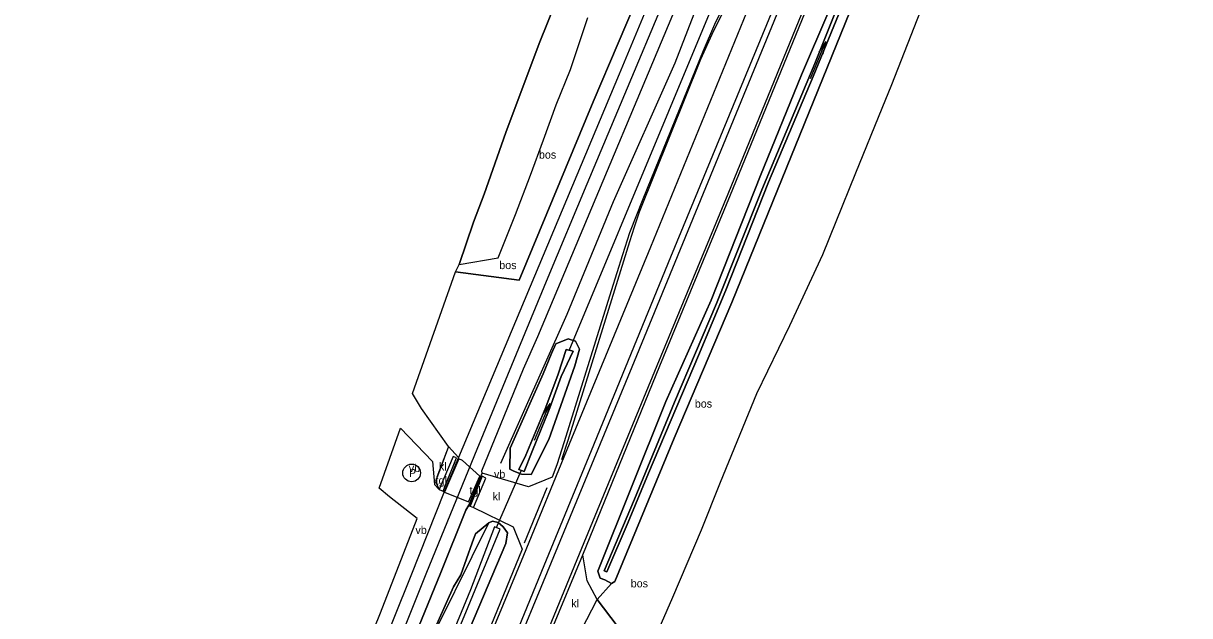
# Model space of a CAD drawing. Extents: x 154825 to 158680, y 370717 to 378075.
# Drawn here: x 158304.8 to 158450.6, y 370834.3 to 370908.4 of the extents above; entities that cross this region are included whole.
import ezdxf

# ---------------------------------------------------------------- set-up
doc = ezdxf.new("R2010")
doc.units = 0
for name, color, linetype in [('bos(vs)', 7, 'Continuous'), ('cultuurscheiding', 7, 'Continuous'), ('deelstreep', 7, 'Continuous'), ('deelstreep(9-3)', 7, 'Continuous'), ('driehoekmarkering', 7, 'Continuous'), ('duiker lijn', 7, 'Continuous'), ('hoogteverschillijn', 7, 'Continuous'), ('insteek sloot', 7, 'Continuous'), ('klinkerverharding(vs)', 7, 'Continuous'), ('maaiveldlijn algemeen - bomenrij', 7, 'Continuous'), ('maaiveldlijn algemeen - gesloten verharding', 7, 'Continuous'), ('maaiveldlijn algemeen - onverhard', 7, 'Continuous'), ('maaiveldlijn algemeen - open verharding', 7, 'Continuous'), ('maaiveldlijn algemeen - tegelverharding', 7, 'Continuous'), ('overstpl br_fietsers', 7, 'Continuous'), ('paal', 7, 'Continuous'), ('Sloot bodem', 7, 'Continuous'), ('stroomrichting  watergangen', 7, 'Continuous'), ('tegelverh(vs)', 7, 'Continuous'), ('verkeersb_z kabel', 7, 'Continuous'), ('vlak_Bos', 7, 'Continuous'), ('vlak_Grazige_vegetatie', 7, 'Continuous')]:
    doc.layers.add(name, color=color, linetype=linetype)

msp = doc.modelspace()

# ---------------------------------------------------------------- linework, layer by layer
at = {"layer": 'cultuurscheiding'}
for points in [[(158357.27, 370849.91), (158357.39, 370849.84)], [(158378.31, 370838.36), (158376.53, 370836.37)]]:
    msp.add_lwpolyline(points, dxfattribs=at)
at = {"layer": 'deelstreep'}
for points in [[(158518.32, 371208.38), (158502.75, 371170.5), (158494.68, 371150.89), (158486.59, 371131.36), (158477.21, 371108.46), (158469.15, 371089.05), (158460.39, 371067.7), (158451.97, 371047.31), (158442.8, 371025.14), (158433.65, 371002.95), (158422.25, 370975.24), (158413.03, 370952.96), (158402.82, 370928.12), (158396.71, 370913.51), (158383.17, 370880.45), (158373.01, 370855.78), (158367.3, 370841.87), (158358.07, 370819.55), (158349.02, 370797.42), (158339.88, 370775.25), (158330.68, 370753.03), (158315.86, 370716.95)], [(158330.81, 370736.28), (158339.92, 370758.92), (158349.12, 370780.82), (158358.22, 370802.88), (158368.66, 370828.28), (158374.3, 370842.09), (158384.02, 370865.65), (158392.9, 370887.13), (158402.15, 370909.74), (158411.25, 370931.72), (158419.96, 370952.82), (158427.75, 370971.73), (158436.98, 370994.2), (158445.74, 371015.21), (158455.27, 371038.51), (158464.46, 371060.72), (158473.59, 371082.89), (158482.88, 371104.99), (158491.72, 371126.78), (158500.78, 371148.75), (158510.14, 371171.51), (158519.32, 371193.88), (158519.33, 371193.79), (158525.55, 371209.02)], [(158370.4, 370876.69), (158375.27, 370888.36), (158389.73, 370922.86), (158396.42, 370939.07), (158403.54, 370956.31), (158412.63, 370978.72), (158420.53, 370997.82), (158429.6, 371019.9), (158436.43, 371036.4), (158443.44, 371053.18), (158450.34, 371070.18), (158457.29, 371087.17), (158465.57, 371107.22), (158473.83, 371127.29), (158479.54, 371141.14), (158491.04, 371168.96), (158498.19, 371186.15), (158506.39, 371203.28)], [(158405.91, 370935.87), (158397.46, 370919.92), (158392.68, 370910.74), (158390.85, 370907.06), (158389.46, 370903.94), (158381.79, 370884.82), (158381.15, 370882.94), (158380.58, 370881.11), (158372.86, 370856.27), (158372.07, 370853.85)], [(158306.26, 370720.32), (158312.93, 370736.4), (158319.74, 370753.08), (158326.57, 370769.69), (158333.4, 370786.4), (158340.27, 370803.09), (158345.89, 370816.78), (158347.17, 370819.9), (158348.37, 370822.82), (158349.48, 370825.56), (158351.75, 370831.03), (158355.16, 370839.59), (158361.25, 370854.48), (158367.54, 370869.73)]]:
    msp.add_lwpolyline(points, dxfattribs=at)
at = {"layer": 'deelstreep(9-3)'}
for points in [[(158521.05, 371207.49), (158505.46, 371169.58), (158497.64, 371150.5), (158489.4, 371130.41), (158479.88, 371107.54), (158471.62, 371087.48), (158463.09, 371066.87), (158454.83, 371046.62), (158445.37, 371023.88), (158436.86, 371003.18), (158424.83, 370974.08), (158416.43, 370953.64), (158405.08, 370926.2), (158399.28, 370912.14), (158385.69, 370879.18), (158375.76, 370854.98), (158369.87, 370840.58), (158361.45, 370820.02), (158353.02, 370799.62), (158339.06, 370765.69), (158329.99, 370743.56)], [(158320.19, 370718), (158328.15, 370737.34), (158335.88, 370756.1), (158345.15, 370778.87), (158353.29, 370798.59), (158364.66, 370826.11), (158371.59, 370842.94), (158381.2, 370866.17), (158390.12, 370887.92), (158399.3, 370910.36), (158408.62, 370932.86), (158417.13, 370953.35), (158425.22, 370973.01), (158434.38, 370995.23), (158443.45, 371017.2), (158452.61, 371039.34), (158461.94, 371061.81), (158470.88, 371083.65), (158480.16, 371106.11), (158489.16, 371127.97), (158498.26, 371150.13), (158507.45, 371172.46)]]:
    msp.add_lwpolyline(points, dxfattribs=at)
at = {"layer": 'driehoekmarkering'}
for points in [[(158367.54, 370869.73), (158370.4, 370876.69)], [(158356.52, 370851.7), (158357.74, 370854.9)], [(158357.45, 370850.41), (158358.76, 370853.62)], [(158361.95, 370851.33), (158360.62, 370848.1)], [(158370.22, 370850.32), (158367.38, 370843.43)]]:
    msp.add_lwpolyline(points, dxfattribs=at)
at = {"layer": 'duiker lijn'}
for points in [[(158373.01, 370867.52), (158397.95, 370927.44)], [(158364.99, 370866.24), (158364.99, 370866.24)], [(158363.96, 370845.37), (158367.02, 370852.47)]]:
    msp.add_lwpolyline(points, dxfattribs=at)
at = {"layer": 'hoogteverschillijn'}
for points in [[(158448.97, 370986.09), (158446.34, 370978.05), (158443.69, 370970.86), (158440.13, 370964.49), (158434.62, 370952.8), (158431.19, 370945.57), (158429.39, 370940.75), (158427.55, 370936.66), (158423.98, 370928.18), (158421.43, 370921.41), (158418.53, 370914.09), (158413.3, 370900.75), (158412.12, 370897.78), (158408.82, 370889.69), (158406.36, 370883.6), (158404.67, 370879.49), (158400.58, 370870.59), (158396.44, 370862.08), (158391.89, 370851), (158389.52, 370845.04), (158385.96, 370836.63), (158383.52, 370831.08)], [(158371.44, 370911.32), (158369.28, 370905.92), (158365.12, 370894.79), (158362.41, 370887.06), (158361.06, 370883.57), (158359.27, 370878.29), (158364.13, 370879.09), (158366.31, 370884.55), (158368.17, 370889.45), (158369.82, 370893.85), (158371.41, 370898.24), (158373.2, 370902.65), (158375.34, 370909.18)]]:
    msp.add_lwpolyline(points, dxfattribs=at)
at = {"layer": 'insteek sloot'}
for points in [[(158433.28, 370971.25), (158433.07, 370971.92), (158432.12, 370972.28), (158431.31, 370972.15), (158430.49, 370970.69), (158422.4, 370951.4), (158415.32, 370934.43), (158408.78, 370917.7), (158402.07, 370901.99), (158396.96, 370889.42), (158390.79, 370873.8), (158385.09, 370861.12), (158376.59, 370839.91), (158376.91, 370839.02), (158377.47, 370838.82), (158378.31, 370838.36)], [(158378.31, 370838.36), (158378.73, 370838.6), (158386.16, 370856.56), (158393.36, 370873.54), (158409.26, 370912.82), (158419.99, 370939.14), (158428.07, 370958.69), (158433.28, 370971.25)], [(158371.37, 370868.37), (158372.89, 370868.97), (158373.82, 370868.69), (158374.3, 370867.67), (158373.74, 370865.61), (158370.49, 370856.38), (158368.27, 370852.02), (158367.06, 370852.04), (158366.1, 370852.41), (158365.62, 370852.68), (158365.66, 370855.31), (158369.78, 370864.59), (158370.83, 370867.12), (158371.37, 370868.37)], [(158364.98, 370866.24), (158364.99, 370866.23)], [(158360.57, 370832.66), (158365.11, 370843.37), (158365.31, 370844.7), (158364.77, 370845.46), (158364.15, 370846.01), (158363.43, 370846.17), (158362.98, 370845.97), (158361.3, 370844.56), (158360.9, 370843.44), (158359.5, 370839.45), (158358.57, 370837.94), (158355.61, 370831.31)]]:
    msp.add_lwpolyline(points, dxfattribs=at)
at = {"layer": 'maaiveldlijn algemeen - bomenrij'}
for points in [[(158417.6, 370980.64), (158410.43, 370964.28), (158402.5, 370945.78), (158393.66, 370922.64), (158386.25, 370903.46), (158378.53, 370886.11), (158372.74, 370872.03), (158364.44, 370853.4)], [(158363, 370846), (158354.42, 370828.73), (158345.77, 370809.19), (158338.93, 370792.65), (158332.35, 370775.25), (158325.05, 370758.01), (158319.07, 370743.02)]]:
    msp.add_lwpolyline(points, dxfattribs=at)
at = {"layer": 'maaiveldlijn algemeen - gesloten verharding'}
for points in [[(158360.5, 370848.18), (158362.16, 370852.19), (158362.1, 370852.46), (158367.33, 370865.21), (158369.11, 370869.26), (158390.25, 370919.7), (158401.42, 370946.95), (158404.71, 370955), (158413.72, 370976.57), (158416.04, 370982.3), (158416.75, 370984.05), (158425.1, 371004.62), (158434.24, 371026.94), (158442.9, 371047.84), (158452.64, 371071.35), (158461.98, 371094.37), (158472.62, 371120.34), (158488.79, 371159.59), (158500.44, 371187.16), (158510.78, 371208.47), (158513.36, 371213.76), (158513.9, 371214.65), (158516.21, 371219.68)], [(158510.96, 371217.04), (158510.54, 371216.03), (158507.65, 371209.81), (158503.9, 371202), (158498.42, 371190.4), (158485.48, 371159.9), (158469.54, 371121.29), (158459.26, 371096.34), (158449.43, 371072.22), (158440.37, 371050.33), (158429.63, 371024.46), (158420.28, 371001.66), (158410.56, 370977.79), (158401.63, 370955.89), (158398.29, 370947.78), (158388.66, 370924.63), (158379.26, 370902.09), (158359.19, 370854.15)], [(158374.72, 370841.95), (158384.36, 370865.6), (158393.18, 370886.99), (158402.48, 370909.7), (158411.6, 370931.56), (158420.31, 370952.71), (158428.1, 370971.71), (158432.47, 370982.24)], [(158424.09, 370980.95), (158423.33, 370979.06), (158412.54, 370952.72), (158407.08, 370939.43), (158404.72, 370934.52), (158401.71, 370928.58), (158397.3, 370919.98), (158392.52, 370910.99), (158391.21, 370908.29), (158389.79, 370904.99), (158382.22, 370886.45), (158380.56, 370882.25), (158379.7, 370879.5), (158378.27, 370874.98), (158372.41, 370856.08), (158371.5, 370853.23), (158370.88, 370851.65)], [(158359.19, 370854.15), (158357.39, 370849.84), (158353.23, 370839.34), (158348.88, 370828.52), (158345.97, 370821.39), (158340.3, 370807.4), (158333.49, 370790.93), (158327.23, 370775.78), (158320.69, 370759.74), (158315.38, 370746.91), (158309.04, 370731.35), (158304.8, 370720.97)], [(158360.5, 370848.18), (158360.09, 370847.53), (158356.98, 370839.76), (158353, 370829.93), (158349.66, 370821.64), (158346.56, 370813.98), (158342.55, 370804.23), (158337.5, 370792.08), (158331.82, 370778.24), (158325.25, 370762.35), (158319, 370747.15), (158313.82, 370734.49), (158307.75, 370719.5)], [(158367.16, 370842.67), (158357.72, 370819.61), (158349.06, 370798.54), (158339.51, 370775.39), (158330.49, 370753.54), (158315.47, 370717.18)], [(158323.21, 370716.85), (158332.11, 370738.39), (158335.76, 370747.27), (158337.66, 370750.57), (158342.42, 370758.9), (158346.72, 370766.94), (158352.16, 370778.23), (158356.68, 370788.88), (158359.65, 370796.2), (158366.07, 370813.5), (158367.59, 370817.72), (158368.34, 370820.83), (158369.1, 370824.38), (158370.46, 370831.48), (158370.84, 370832.6), (158374.72, 370841.95)]]:
    msp.add_lwpolyline(points, dxfattribs=at)
at = {"layer": 'maaiveldlijn algemeen - onverhard'}
for points in [[(158505.46, 371210.98), (158499.23, 371197.15), (158490.43, 371177.02), (158481.73, 371156.69), (158473.78, 371136.07), (158465.69, 371118.29), (158458.24, 371101.07), (158450.67, 371081.54), (158444.43, 371066.59), (158435.41, 371045.45), (158427.28, 371024.84), (158418.08, 371003.2), (158410.98, 370985.37), (158401.57, 370959.61), (158393.95, 370941.07), (158385.41, 370920.7), (158376.04, 370898.61), (158366.77, 370876.33), (158358.83, 370877.35)], [(158357.92, 370855.5), (158354.58, 370860.25), (158353.46, 370862.12)], [(158351.94, 370857.82), (158355.92, 370853.62), (158356.17, 370850.77), (158356.77, 370850.12)], [(158313.02, 370745.72), (158320.68, 370764.69), (158328.9, 370784.64), (158336.09, 370801.64), (158341.21, 370814.19), (158344.17, 370821.6), (158349.44, 370834.69), (158354.02, 370846.5), (158350.55, 370849.22), (158349.28, 370850.28)], [(158376.53, 370836.37), (158380.72, 370830.8), (158383.98, 370825.89), (158386.59, 370821.47), (158387.81, 370819.28), (158390.57, 370817), (158385.07, 370810.93), (158384.03, 370815.72), (158380.99, 370822.15), (158378.43, 370827), (158374.57, 370832.59)]]:
    msp.add_lwpolyline(points, dxfattribs=at)
at = {"layer": 'maaiveldlijn algemeen - open verharding'}
for points in [[(158359.19, 370854.15), (158357.92, 370855.5), (158356.3, 370851.11), (158356.77, 370850.12)], [(158370.88, 370851.65), (158367.95, 370850.45), (158362.16, 370852.19)], [(158360.5, 370848.18), (158360.63, 370848.06), (158361.06, 370847.87), (158366.01, 370845.45), (158367.16, 370842.67)], [(158374.57, 370832.59), (158376.53, 370836.37), (158375.29, 370838.7), (158374.72, 370841.95)]]:
    msp.add_lwpolyline(points, dxfattribs=at)
at = {"layer": 'maaiveldlijn algemeen - tegelverharding'}
for points in [[(158357.27, 370849.91), (158358.93, 370854.07), (158358.51, 370854.26), (158356.77, 370850.12), (158357.27, 370849.91)], [(158360.63, 370848.06), (158361.06, 370847.87), (158362.6, 370851.54), (158362.15, 370851.8), (158360.63, 370848.06)]]:
    msp.add_lwpolyline(points, dxfattribs=at)
at = {"layer": 'overstpl br_fietsers'}
msp.add_lwpolyline([(158360.46, 370848.6), (158361.84, 370851.8), (158359.67, 370853.77), (158359.23, 370853.96), (158357.46, 370849.8), (158360.46, 370848.6)], dxfattribs=at)
at = {"layer": 'paal'}
msp.add_circle((158353.33, 370852.2), 1.1, dxfattribs=at)
at = {"layer": 'Sloot bodem'}
for points in [[(158409.96, 370917.49), (158403.53, 370901.81), (158397.96, 370888.57), (158392.61, 370875.05), (158389.18, 370866.91), (158382.93, 370852.18), (158380.4, 370846.06), (158377.72, 370839.82), (158377.41, 370839.95), (158381.18, 370848.91), (158386.19, 370861.06), (158391.42, 370873.38), (158397.09, 370887.62), (158403.74, 370903.43), (158410.06, 370919.3)], [(158367.41, 370852.38), (158366.72, 370852.63), (158367.61, 370854.41), (158370.12, 370860.43), (158371.66, 370864.56), (158372.65, 370867.66), (158373.54, 370867.45), (158372.02, 370864.28), (158370.59, 370860.35), (158368.34, 370854.79), (158367.41, 370852.38)], [(158364.4, 370845.17), (158363.7, 370845.44), (158360.69, 370837.57), (158355.01, 370823.83), (158348.36, 370807.96), (158343.27, 370795.8), (158336.18, 370778.79), (158332.92, 370770.56), (158328.04, 370758.89), (158324.18, 370749.71), (158318.24, 370735.1), (158311.09, 370717.82), (158311.7, 370717.65), (158318.19, 370733.77), (158324.83, 370749.82), (158331.49, 370765.68), (158338.43, 370782.48), (158345.71, 370800.27), (158350.95, 370812.9), (158354.38, 370820.96), (158360.4, 370835.46), (158364.4, 370845.17)]]:
    msp.add_lwpolyline(points, dxfattribs=at)
at = {"layer": 'stroomrichting  watergangen'}
for p, q in [((158403.18, 370901.55), (158405.09, 370906.17)), ((158405.09, 370906.17), (158404.24, 370904.83)), ((158405.09, 370906.15), (158404.75, 370904.6)), ((158368.68, 370856.28), (158370.59, 370860.9)), ((158370.59, 370860.9), (158369.74, 370859.57)), ((158370.59, 370860.88), (158370.25, 370859.34))]:
    msp.add_line(p, q, dxfattribs=at)
at = {"layer": 'vlak_Bos'}
for points in [[(158380.72, 370830.8), (158376.53, 370836.37), (158378.31, 370838.36), (158378.73, 370838.6), (158386.16, 370856.56), (158393.36, 370873.54), (158409.26, 370912.82), (158419.99, 370939.14), (158428.07, 370958.69), (158433.28, 370971.25), (158437.82, 370980.04), (158446.21, 371001.24)], [(158410.98, 370985.37), (158401.57, 370959.61), (158393.95, 370941.07), (158385.41, 370920.7), (158376.04, 370898.61), (158366.77, 370876.33), (158358.83, 370877.35), (158359.27, 370878.29), (158361.06, 370883.57), (158362.41, 370887.06), (158365.12, 370894.79), (158369.28, 370905.92), (158371.44, 370911.32), (158374.49, 370918.35), (158377.68, 370926.3), (158380.7, 370934.51), (158382.69, 370939.88), (158384.75, 370945.26), (158388.8, 370955.93), (158391.22, 370962.74), (158394.57, 370971.87), (158399.01, 370984.64)], [(158448.97, 370986.09), (158446.34, 370978.05), (158443.69, 370970.86), (158440.13, 370964.49), (158434.62, 370952.8), (158431.19, 370945.57), (158429.39, 370940.75), (158427.55, 370936.66), (158423.98, 370928.18), (158421.43, 370921.41), (158418.53, 370914.09), (158413.3, 370900.75), (158412.12, 370897.78), (158408.82, 370889.69), (158406.36, 370883.6), (158404.67, 370879.49), (158400.58, 370870.59), (158396.44, 370862.08), (158391.89, 370851), (158389.52, 370845.04), (158385.96, 370836.63), (158383.52, 370831.08)]]:
    msp.add_lwpolyline(points, dxfattribs=at)
at = {"layer": 'vlak_Grazige_vegetatie'}
for points in [[(158420.28, 371001.66), (158410.56, 370977.79), (158401.63, 370955.89), (158398.29, 370947.78), (158388.66, 370924.63), (158379.26, 370902.09), (158359.19, 370854.15), (158357.92, 370855.5), (158354.58, 370860.25), (158353.46, 370862.12), (158358.83, 370877.35), (158366.77, 370876.33), (158376.04, 370898.61), (158385.41, 370920.7), (158393.95, 370941.07), (158401.57, 370959.61), (158410.98, 370985.37)], [(158392.52, 370910.99), (158391.21, 370908.29), (158389.79, 370904.99), (158382.22, 370886.45), (158380.56, 370882.25), (158379.7, 370879.5), (158378.27, 370874.98), (158372.41, 370856.08), (158371.5, 370853.23), (158370.88, 370851.65), (158367.95, 370850.45), (158362.16, 370852.19), (158362.1, 370852.46), (158367.33, 370865.21), (158369.11, 370869.26), (158390.25, 370919.7)], [(158408.78, 370917.7), (158402.07, 370901.99), (158396.96, 370889.42), (158390.79, 370873.8), (158385.09, 370861.12), (158376.59, 370839.91), (158376.91, 370839.02), (158377.47, 370838.82), (158378.31, 370838.36), (158376.53, 370836.37), (158375.29, 370838.7), (158374.72, 370841.95), (158384.36, 370865.6), (158393.18, 370886.99), (158402.48, 370909.7)], [(158344.17, 370821.6), (158349.44, 370834.69), (158354.02, 370846.5), (158350.55, 370849.22), (158349.28, 370850.28), (158351.94, 370857.82), (158355.92, 370853.62), (158356.17, 370850.77), (158356.77, 370850.12), (158357.27, 370849.91), (158357.39, 370849.84), (158353.23, 370839.34), (158348.88, 370828.52)], [(158353, 370829.93), (158356.98, 370839.76), (158360.09, 370847.53), (158360.5, 370848.18), (158360.63, 370848.06), (158361.06, 370847.87), (158366.01, 370845.45), (158367.16, 370842.67), (158357.72, 370819.61)], [(158354.38, 370820.96), (158360.4, 370835.46), (158364.4, 370845.17), (158363.7, 370845.44), (158360.69, 370837.57), (158355.01, 370823.83)], [(158360.57, 370832.66), (158365.11, 370843.37), (158365.31, 370844.7), (158364.77, 370845.46), (158364.15, 370846.01), (158363.43, 370846.17), (158362.98, 370845.97), (158361.3, 370844.56), (158360.9, 370843.44), (158359.5, 370839.45), (158358.57, 370837.94), (158355.61, 370831.31)], [(158355.61, 370831.31), (158358.57, 370837.94), (158359.5, 370839.45), (158360.9, 370843.44), (158361.3, 370844.56), (158362.98, 370845.97), (158363.43, 370846.17), (158364.15, 370846.01), (158364.77, 370845.46), (158365.31, 370844.7), (158365.11, 370843.37), (158360.57, 370832.66)]]:
    msp.add_lwpolyline(points, dxfattribs=at)
for points in [[(158433.07, 370971.92), (158433.28, 370971.25), (158428.07, 370958.69), (158419.99, 370939.14), (158409.26, 370912.82), (158393.36, 370873.54), (158386.16, 370856.56), (158378.73, 370838.6), (158378.31, 370838.36), (158377.47, 370838.82), (158376.91, 370839.02), (158376.59, 370839.91), (158385.09, 370861.12), (158390.79, 370873.8), (158396.96, 370889.42), (158402.07, 370901.99), (158408.78, 370917.7), (158415.32, 370934.43), (158422.4, 370951.4), (158430.49, 370970.69), (158431.31, 370972.15), (158432.12, 370972.28)], [(158377.41, 370839.95), (158377.72, 370839.82), (158380.4, 370846.06), (158382.93, 370852.18), (158389.18, 370866.91), (158392.61, 370875.05), (158397.96, 370888.57), (158403.53, 370901.81), (158409.96, 370917.49), (158418.16, 370937.71), (158423.58, 370951.08), (158430.77, 370968.54), (158432.23, 370971.36), (158431.61, 370971.67), (158430.14, 370968.23), (158428.41, 370964.23), (158424.22, 370954.04), (158417.68, 370936.81), (158410.06, 370919.3), (158403.74, 370903.43), (158397.09, 370887.62), (158391.42, 370873.38), (158386.19, 370861.06), (158381.18, 370848.91)], [(158367.06, 370852.04), (158368.27, 370852.02), (158370.49, 370856.38), (158373.74, 370865.61), (158374.3, 370867.67), (158373.82, 370868.69), (158372.89, 370868.97), (158371.37, 370868.37), (158370.83, 370867.12), (158369.78, 370864.59), (158365.66, 370855.31), (158365.62, 370852.68), (158366.1, 370852.41)], [(158374.3, 370867.67), (158373.74, 370865.61), (158370.49, 370856.38), (158368.27, 370852.02), (158367.06, 370852.04), (158366.1, 370852.41), (158365.62, 370852.68), (158365.66, 370855.31), (158369.78, 370864.59), (158370.83, 370867.12), (158371.37, 370868.37), (158372.89, 370868.97), (158373.82, 370868.69)], [(158366.72, 370852.63), (158367.41, 370852.38), (158368.34, 370854.79), (158370.59, 370860.35), (158372.02, 370864.28), (158373.54, 370867.45), (158372.65, 370867.66), (158371.66, 370864.56), (158370.12, 370860.43), (158367.61, 370854.41)]]:
    msp.add_lwpolyline(points, close=True, dxfattribs=at)

# ---------------------------------------------------------------- texts
at = {"layer": 'bos(vs)'}
for p in [(158369.25, 370891.52), (158364.29, 370877.7), (158388.73, 370860.37), (158380.72, 370837.88)]:
    msp.add_text('bos', height=1, dxfattribs=at).set_placement(p)
at = {"layer": 'klinkerverharding(vs)'}
for p in [(158356.75, 370852.5), (158363.46, 370848.77), (158373.29, 370835.39)]:
    msp.add_text('kl', height=1, dxfattribs=at).set_placement(p)
at = {"layer": 'paal'}
msp.add_text('P', height=1, dxfattribs=at).set_placement((158353, 370851.7))
at = {"layer": 'tegelverh(vs)'}
for p in [(158356.33, 370850.76), (158360.56, 370849.51)]:
    msp.add_text('tgl', height=1, dxfattribs=at).set_placement(p)
at = {"layer": 'verkeersb_z kabel'}
for p in [(158352.98, 370852.32), (158363.63, 370851.56), (158353.81, 370844.56)]:
    msp.add_text('vb', height=1, dxfattribs=at).set_placement(p)

doc.saveas('drawing.dxf')
